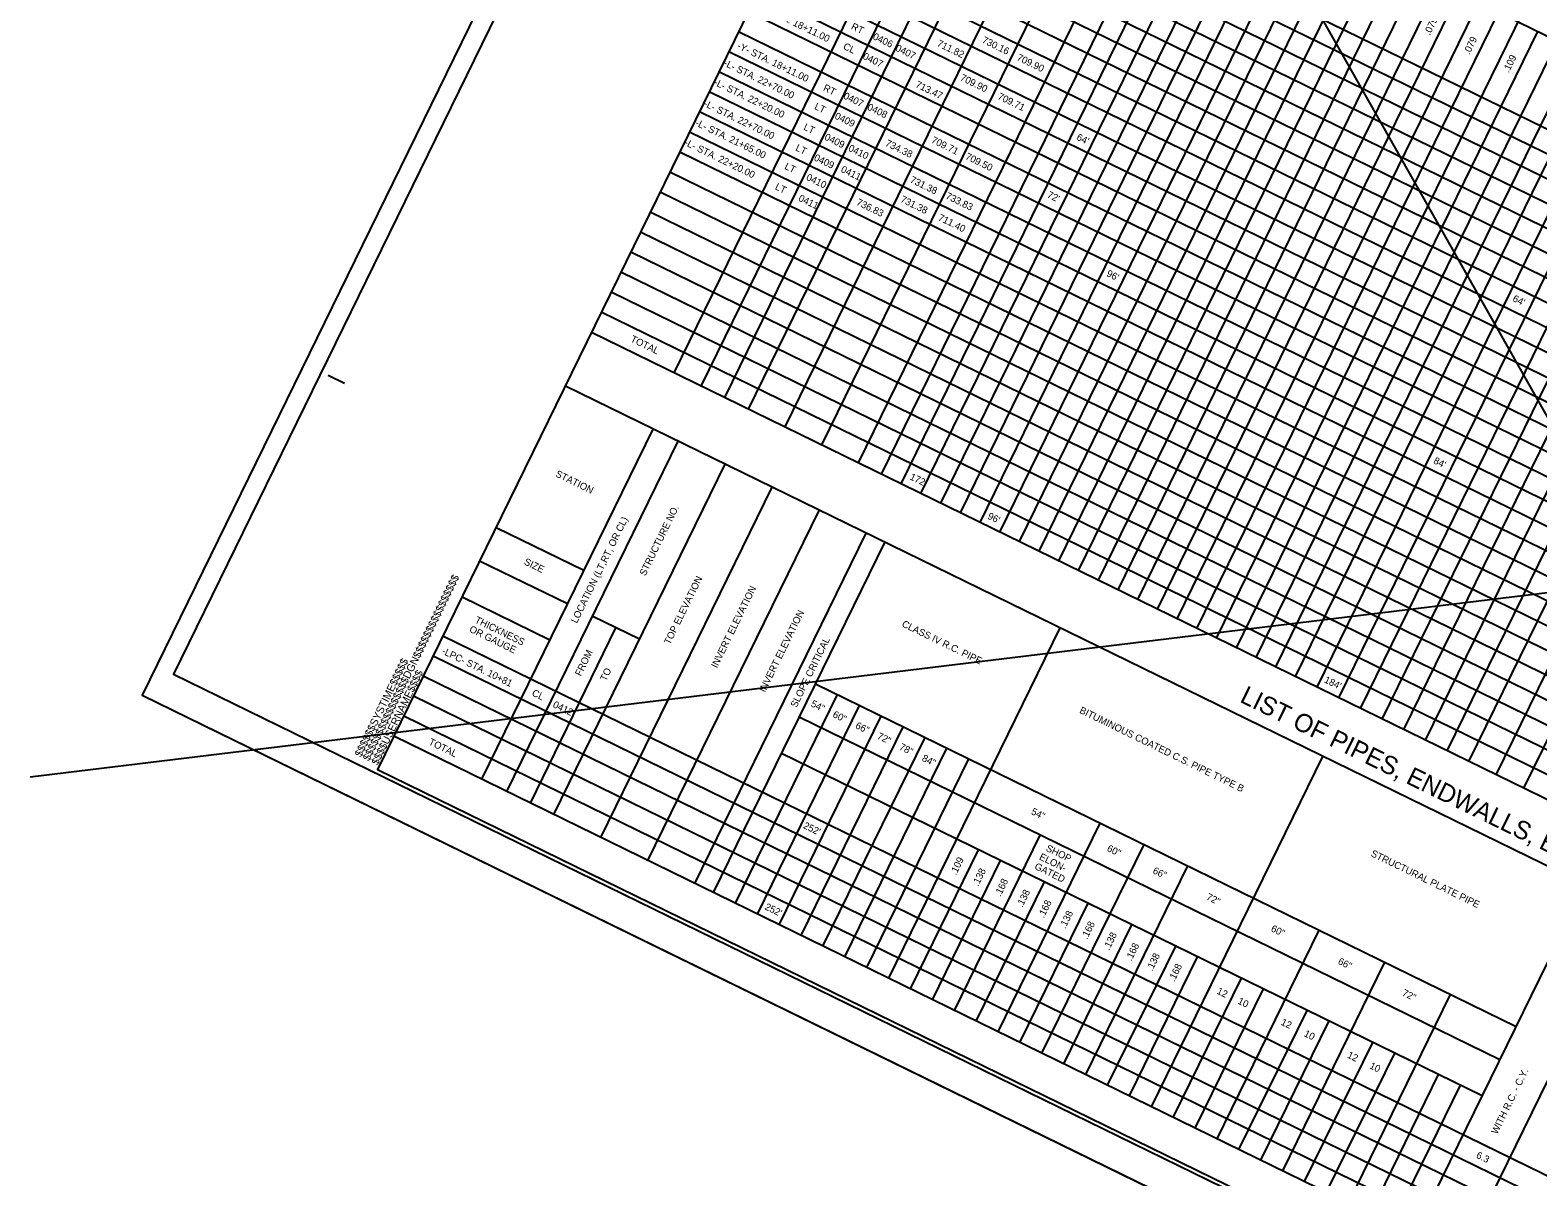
# Model space of a CAD drawing. Extents: x 1523741 to 1527628, y 632733 to 635404.
# Drawn here: x 1523741 to 1524772, y 634021 to 634805 of the extents above; entities that cross this region are included whole.
import ezdxf

# ---------------------------------------------------------------- set-up
doc = ezdxf.new("R2010")
doc.units = 0
for name, color, linetype in [('Scratch_Level_0', 7, 'Continuous'), ('Sheet Cutting Line CELL', 7, 'Continuous'), ('Sheet Pipe Summary CELL', 7, 'Continuous'), ('Sheet Pipe Summary Grid CELL', 7, 'Continuous'), ('Sheet Plot Border Inside CELL', 7, 'Continuous'), ('Sheet Plot Border Outside CELL', 7, 'Continuous'), ('Sheet Summary Combination CELL', 7, 'Continuous'), ('Sheet Summary Combination Grid CELL', 7, 'Continuous')]:
    doc.layers.add(name, color=color, linetype=linetype)

msp = doc.modelspace()

# ---------------------------------------------------------------- linework, layer by layer
at = {"layer": 'Scratch_Level_0'}
for p, q in [((1525401.8, 633436.6), (1524290.2, 635404.2)), ((1523740.9, 634294.4), (1525923.1, 634560))]:
    msp.add_line(p, q, dxfattribs=at)
at = {"layer": 'Sheet Cutting Line CELL'}
for p, q in [((1524300.8, 635338.5), (1523817.5, 634350.4)), ((1523817.5, 634350.4), (1525330.3, 633610.5))]:
    msp.add_line(p, q, dxfattribs=at)
at = {"layer": 'Sheet Pipe Summary Grid CELL'}
for p, q in [((1524181.3, 634570.7), (1524445.8, 635111.6)), ((1524199.7, 634561.7), (1524464.3, 635102.6)), ((1524231.9, 634546), (1524496.4, 635086.9)), ((1524257, 634533.7), (1524521.5, 635074.6)), ((1524282.1, 634521.4), (1524546.6, 635062.3)), ((1524307.2, 634509.1), (1524571.8, 635050)), ((1524323, 634501.4), (1524587.5, 635042.3)), ((1524376.9, 634475), (1524641.4, 635016)), ((1524430.8, 634448.7), (1524695.3, 634989.6)), ((1524215.8, 634553.8), (1524421.8, 634975)), ((1525653.1, 634309.3), (1524305.6, 634968.3)), ((1525646.4, 634295.6), (1524298.9, 634954.6)), ((1525639.7, 634281.9), (1524292.2, 634940.9)), ((1524336.4, 634494.8), (1524553.6, 634938.9)), ((1525633, 634268.2), (1524285.5, 634927.2)), ((1524349.9, 634488.2), (1524567.1, 634932.3)), ((1524363.4, 634481.6), (1524580.5, 634925.7)), ((1524376.9, 634475), (1524594, 634919.1)), ((1524930.5, 634726.3), (1524529, 634922.7)), ((1525626.3, 634254.4), (1524278.8, 634913.5)), ((1524390.3, 634468.5), (1524607.5, 634912.5)), ((1524403.8, 634461.9), (1524621, 634905.9)), ((1525619.6, 634240.7), (1524272.1, 634899.8)), ((1524417.3, 634455.3), (1524634.4, 634899.3)), ((1524605.9, 634363), (1524870.5, 634904)), ((1525612.9, 634227), (1524265.4, 634886.1)), ((1524444.2, 634442.1), (1524661.4, 634886.2)), ((1524457.7, 634435.5), (1524674.9, 634879.6)), ((1525606.2, 634213.3), (1524258.7, 634872.4)), ((1524471.2, 634428.9), (1524688.3, 634873)), ((1525599.5, 634199.6), (1524252, 634858.7)), ((1524498.1, 634415.7), (1524715.3, 634859.8)), ((1525592.8, 634185.9), (1524245.3, 634845)), ((1524484.7, 634422.3), (1524690.7, 634843.6)), ((1524525.1, 634402.6), (1524742.2, 634846.6)), ((1524724.5, 634305), (1524989.1, 634846.1)), ((1524552, 634389.4), (1524769.2, 634833.4)), ((1524743.1, 634295.9), (1525007.7, 634837)), ((1525586.1, 634172.2), (1524238.6, 634831.3)), ((1524511.6, 634409.1), (1524717.6, 634830.4)), ((1524762, 634286.7), (1525026.7, 634827.8)), ((1525579.4, 634158.5), (1524231.9, 634817.6)), ((1524538.6, 634396), (1524744.6, 634817.2)), ((1524579, 634376.2), (1524796.1, 634820.3)), ((1525572.7, 634144.8), (1524225.2, 634803.9)), ((1524565.5, 634382.8), (1524771.5, 634804.1)), ((1524620.8, 634355.8), (1524837.9, 634799.9)), ((1524635.6, 634348.5), (1524852.8, 634792.6)), ((1525566, 634131.1), (1524218.5, 634790.2)), ((1524592.5, 634369.6), (1524798.5, 634790.9)), ((1524650.4, 634341.3), (1524867.6, 634785.4)), ((1525559.3, 634117.4), (1524211.8, 634776.5)), ((1524665.2, 634334), (1524882.4, 634778.1)), ((1525552.6, 634103.7), (1524205.1, 634762.8)), ((1524680, 634326.8), (1524897.2, 634770.9)), ((1524694.9, 634319.5), (1524912, 634763.6)), ((1524709.7, 634312.3), (1524926.9, 634756.4)), ((1525545.9, 634090), (1524198.4, 634749.1)), ((1525539.2, 634076.3), (1524191.7, 634735.4)), ((1525532.5, 634062.6), (1524185, 634721.7)), ((1525525.8, 634048.9), (1524178.3, 634708)), ((1525519.1, 634035.2), (1524171.6, 634694.3)), ((1525512.4, 634021.5), (1524164.9, 634680.6)), ((1525505.7, 634007.8), (1524158.2, 634666.9)), ((1525499, 633994.1), (1524151.5, 634653.2)), ((1525492.3, 633980.4), (1524144.8, 634639.5)), ((1525485.6, 633966.7), (1524138.1, 634625.8)), ((1525478.9, 633953.1), (1524131.4, 634612.1)), ((1525478.9, 633953.1), (1524131.4, 634612.1)), ((1525472.2, 633939.4), (1524124.7, 634598.4)), ((1525472.2, 633939.4), (1524124.7, 634598.4))]:
    msp.add_line(p, q, dxfattribs=at)
at = {"layer": 'Sheet Plot Border Inside CELL'}
msp.add_lwpolyline([(1525799.6, 634580.5), (1524302.6, 635312.6), (1523839, 634364.8), (1525336.1, 633632.6)], close=True, dxfattribs=at)
at = {"layer": 'Sheet Plot Border Outside CELL'}
msp.add_lwpolyline([(1525813.5, 634598.6), (1524300.8, 635338.5), (1523817.5, 634350.4), (1525330.3, 633610.5)], close=True, dxfattribs=at)
at = {"layer": 'Sheet Summary Combination CELL'}
for p, q in [((1523944.7, 634569.2), (1523955.9, 634563.7)), ((1523978.5, 634299.4), (1523978.5, 634299.4))]:
    msp.add_line(p, q, dxfattribs=at)
msp.add_lwpolyline([(1525787.3, 634583.7), (1524439.8, 635242.7), (1523978.5, 634299.4), (1525326, 633640.4)], close=True, dxfattribs=at)
at = {"layer": 'Sheet Summary Combination Grid CELL'}
for p, q in [((1525454.3, 633902.8), (1524106.8, 634561.7)), ((1524049.7, 634292.8), (1524166.8, 634532.2)), ((1524066.8, 634284.4), (1524183.9, 634523.9)), ((1524098.9, 634268.8), (1524216, 634508.2)), ((1524131, 634253), (1524248.1, 634492.5)), ((1524163.2, 634237.3), (1524280.3, 634476.7)), ((1524119.4, 634435.5), (1524059.4, 634464.8)), ((1524195.4, 634221.6), (1524312.5, 634461)), ((1524208.1, 634215.3), (1524325.2, 634454.8)), ((1524108.3, 634412.7), (1524048.2, 634442)), ((1524096.2, 634388), (1524036.2, 634417.4)), ((1524157.5, 634388.6), (1524125.5, 634404.2)), ((1525370.6, 633731.7), (1524023.1, 634390.7)), ((1524082.9, 634276.6), (1524141.4, 634396.3)), ((1524327.9, 634156.8), (1524445, 634396.3)), ((1525363.9, 633718), (1524016.4, 634377)), ((1525357.2, 633704.3), (1524009.7, 634363.3)), ((1524265.1, 634364.1), (1524265.1, 634364.1)), ((1525350.5, 633690.6), (1524003, 634349.6)), ((1524221.8, 634357), (1524221.8, 634357)), ((1524223.1, 634208), (1524292.8, 634350.7)), ((1524277.9, 634358), (1524756.8, 634123.8)), ((1524238.1, 634200.7), (1524307.8, 634343.3)), ((1524254, 634341.3), (1524253.9, 634341.3)), ((1525343.8, 633676.9), (1523996.3, 634335.9)), ((1525343.8, 633676.9), (1523996.3, 634335.9)), ((1524253, 634193.4), (1524322.8, 634336)), ((1524745.7, 634101), (1524266.7, 634335.2)), ((1524268, 634186.1), (1524337.7, 634328.7)), ((1525337.1, 633663.2), (1523989.6, 634322.2)), ((1524282.9, 634178.7), (1524352.7, 634321.4)), ((1524733.6, 634076.3), (1524254.6, 634310.5)), ((1524297.9, 634171.4), (1524367.7, 634314.1)), ((1524507.5, 634068.9), (1524624.6, 634308.5)), ((1524312.9, 634164.1), (1524382.6, 634306.7)), ((1524402.7, 634120.2), (1524472.5, 634262.9)), ((1524372.8, 634134.8), (1524431.4, 634254.7)), ((1524432.6, 634105.5), (1524502.4, 634248.2)), ((1524342.8, 634149.5), (1524389.3, 634244.6)), ((1524357.8, 634142.1), (1524404.3, 634237.3)), ((1524462.6, 634090.9), (1524532.4, 634233.6)), ((1524387.7, 634127.5), (1524434.3, 634222.7)), ((1524687, 633981.1), (1524804.2, 634220.6)), ((1524417.6, 634112.9), (1524464.2, 634208)), ((1524447.6, 634098.2), (1524494.1, 634193.4)), ((1524552.3, 634047), (1524622.1, 634189.7)), ((1524477.5, 634083.6), (1524524.1, 634178.7)), ((1524492.5, 634076.3), (1524539, 634171.4)), ((1524597.3, 634025), (1524667.1, 634167.7)), ((1524522.4, 634061.6), (1524569, 634156.8)), ((1524537.4, 634054.3), (1524584, 634149.5)), ((1524642.2, 634003), (1524711.9, 634145.7)), ((1524567.3, 634039.6), (1524613.9, 634134.8)), ((1524719, 633965.5), (1524803.6, 634138.6)), ((1524582.3, 634032.3), (1524628.9, 634127.6)), ((1524612.2, 634017.7), (1524658.8, 634112.9)), ((1524627.2, 634010.4), (1524673.8, 634105.6)), ((1524657.1, 633995.7), (1524703.7, 634091)), ((1524672.1, 633988.4), (1524718.7, 634083.6))]:
    msp.add_line(p, q, dxfattribs=at)

# ---------------------------------------------------------------- texts
at = {"layer": 'Sheet Pipe Summary CELL'}
for s, p in [('.079', (1524697.8, 634801.2)), ('.079', (1524724.8, 634787.9)), ('.109', (1524751.7, 634775.5))]:
    msp.add_text(s, height=4.8, rotation=63.9377, dxfattribs=at).set_placement(p)
at = {"layer": 'Sheet Summary Combination CELL'}
for s, height, rotation, p in [('-Y- STA. 18+11.00', 4.8, 333.9377, (1524238.2, 634820.1)), ('RT', 4.8, 333.9377, (1524301.7, 634806)), ('0406', 4.8, 333.9377, (1524316.5, 634799.1)), ('-Y- STA. 18+11.00', 4.8, 333.9377, (1524223.8, 634792.8)), ('CL', 4.8, 333.9377, (1524296.3, 634792.4)), ('0407', 4.8, 333.9377, (1524332, 634791.2)), ('711.82', 4.8, 333.9377, (1524360.4, 634794.4)), ('730.16', 4.8, 333.9377, (1524391.2, 634796.7)), ('-L- STA. 22+70.00', 4.8, 333.9377, (1524214.6, 634781)), ('0407', 4.8, 333.9377, (1524309.7, 634785.6)), ('709.90', 4.8, 333.9377, (1524415, 634784.8)), ('709.90', 4.8, 333.9377, (1524376.3, 634771)), ('-L- STA. 22+20.00', 4.8, 333.9377, (1524207.9, 634767.9)), ('RT', 4.8, 333.9377, (1524282.6, 634764)), ('0407', 4.8, 333.9377, (1524296.4, 634758.5)), ('713.47', 4.8, 333.9377, (1524345.7, 634766.3)), ('709.71', 4.8, 333.9377, (1524401.9, 634758.2)), ('-L- STA. 22+70.00', 4.8, 333.9377, (1524201, 634753.3)), ('LT', 4.8, 333.9377, (1524276.6, 634751.3)), ('0408', 4.8, 333.9377, (1524312.7, 634750.9)), ('-L- STA. 21+65.00', 4.8, 333.9377, (1524195.2, 634740.1)), ('LT', 4.8, 333.9377, (1524269.2, 634737.2)), ('0409', 4.8, 333.9377, (1524290.5, 634744.8)), ('0409', 4.8, 333.9377, (1524283.5, 634730.4)), ('734.38', 4.8, 333.9377, (1524325.1, 634726.2)), ('709.71', 4.8, 333.9377, (1524356.5, 634728.3)), ("64'", 4.8, 333.9377, (1524455.8, 634730.3)), ('-L- STA. 22+20.00', 4.8, 333.9377, (1524187.7, 634726.7)), ('LT', 4.8, 333.9377, (1524263.7, 634723)), ('0409', 4.8, 333.9377, (1524276.3, 634716.3)), ('0410', 4.8, 333.9377, (1524299.8, 634722.8)), ('709.50', 4.8, 333.9377, (1524379.8, 634717.1)), ('LT', 4.8, 333.9377, (1524256.2, 634710.4)), ('0411', 4.8, 333.9377, (1524294.7, 634708.3)), ('LT', 4.8, 333.9377, (1524249.7, 634696.4)), ('0410', 4.8, 333.9377, (1524271, 634702.9)), ('731.38', 4.8, 333.9377, (1524342, 634701.2)), ('0411', 4.8, 333.9377, (1524265.7, 634688.6)), ('736.83', 4.8, 333.9377, (1524305.3, 634685.8)), ('731.38', 4.8, 333.9377, (1524335.4, 634687.8)), ('733.83', 4.8, 333.9377, (1524366.3, 634690.1)), ("72'", 4.8, 333.9377, (1524435.7, 634690.9)), ('711.40', 4.8, 333.9377, (1524361.2, 634675.3)), ("96'", 4.8, 333.9377, (1524476.3, 634637.1)), ("64'", 4.8, 333.9377, (1524753.9, 634620)), ('TOTAL', 4.8, 333.9377, (1524150.9, 634592.3)), ('STATION', 4.8, 333.9377, (1524099.6, 634500.1)), ("84'", 4.8, 333.9377, (1524699.8, 634509.1)), ("172'", 4.8, 333.9377, (1524341.8, 634498.1)), ('STRUCTURE NO.', 4.8, 63.9377, (1524161.5, 634431.5)), ("96'", 4.8, 333.9377, (1524395, 634471.2)), ('LOCATION (LT,RT, OR CL)', 4.8, 63.9377, (1524114.7, 634399.1)), ('SIZE', 4.8, 333.9377, (1524078.1, 634440)), ('$$$$$$$$$$$$$$$$DGN$$$$$$$$$$$$$$$$', 5.25, 63.9377, (1523972.7, 634304.9)), ('TOP ELEVATION', 4.8, 63.9377, (1524178.3, 634384.5)), ('INVERT ELEVATION', 4.8, 63.9377, (1524210.5, 634368.5)), ('THICKNESS', 4.8, 333.9377, (1524044.5, 634400.2)), ('INVERT ELEVATION', 4.8, 63.9377, (1524243.3, 634351.9)), ('CLASS IV R.C. PIPE', 4.8, 333.9377, (1524336.4, 634397.5)), ('OR GAUGE', 4.8, 333.9377, (1524040.7, 634393.9)), ('-LPC- STA. 10+81', 4.8, 333.9377, (1524021.9, 634379)), ('FROM', 4.8, 63.9377, (1524117.4, 634362.9)), ('SLOPE CRITICAL', 4.8, 63.9377, (1524264.8, 634341.4)), ('$$$$$$SYSTIME$$$$$', 5.25, 63.9377, (1523967.2, 634307.6)), ('$$$$USERNAME$$$$', 5.25, 63.9377, (1523978.6, 634302.1)), ('TO', 4.8, 63.9377, (1524134.6, 634359.5)), ("184'", 4.8, 333.9377, (1524625.1, 634359.3)), ('CL', 4.8, 333.9377, (1524083.5, 634350.3)), ('LIST OF PIPES, ENDWALLS, ETC. (FOR PIPES 54" & OVER)', 12.5, 333.9377, (1524567.2, 634346)), ('0412', 4.8, 333.9377, (1524097.8, 634342.3)), ('54"', 4.8, 333.9377, (1524274.2, 634342.9)), ('60"', 4.8, 333.9377, (1524289.1, 634335.6)), ('BITUMINOUS COATED C.S. PIPE TYPE B', 4.8, 333.9377, (1524457.8, 634338.4)), ('66"', 4.8, 333.9377, (1524304.6, 634328)), ('TOTAL', 4.8, 333.9377, (1524012.9, 634316.8)), ('72"', 4.8, 333.9377, (1524319.5, 634320.8)), ('78"', 4.8, 333.9377, (1524334.6, 634313.4)), ('84"', 4.8, 333.9377, (1524350.1, 634305.7)), ('54"', 4.8, 333.9377, (1524424.8, 634269.2)), ("252'", 4.8, 333.9377, (1524269, 634259.6)), ('SHOP', 4.8, 333.9377, (1524434.9, 634244.1)), ('60"', 4.8, 333.9377, (1524476.6, 634244)), ('.109', 4.8, 63.9377, (1524373.9, 634226.9)), ('ELON-', 4.8, 333.9377, (1524430.3, 634238.2)), ('STRUCTURAL PLATE PIPE', 4.8, 333.9377, (1524657, 634240.5)), ('.138', 4.8, 63.9377, (1524389, 634219.3)), ('GATED', 4.8, 333.9377, (1524427.1, 634231.7)), ('66"', 4.8, 333.9377, (1524507.9, 634228.8)), ('.168', 4.8, 63.9377, (1524404.2, 634212.2)), ('.138', 4.8, 63.9377, (1524419.2, 634204.7)), ('72"', 4.8, 333.9377, (1524544.5, 634210.8)), ("252'", 4.8, 333.9377, (1524242.7, 634204.1)), ('.168', 4.8, 63.9377, (1524433.9, 634197.6)), ('.138', 4.8, 63.9377, (1524448.6, 634190.3)), ('.168', 4.8, 63.9377, (1524463.5, 634183)), ('.138', 4.8, 63.9377, (1524478.6, 634175.6)), ('60"', 4.8, 333.9377, (1524588.7, 634189.2)), ('.168', 4.8, 63.9377, (1524493.8, 634168.2)), ('.138', 4.8, 63.9377, (1524508, 634161.3)), ('.168', 4.8, 63.9377, (1524523.1, 634154)), ('66"', 4.8, 333.9377, (1524634.5, 634166.8)), ('12', 4.8, 333.9377, (1524551.7, 634146.4)), ('10', 4.8, 333.9377, (1524566, 634139.6)), ('72"', 4.8, 333.9377, (1524678.4, 634145.2)), ('12', 4.8, 333.9377, (1524595.5, 634125.2)), ('10', 4.8, 333.9377, (1524611.3, 634117.4)), ('12', 4.8, 333.9377, (1524640.9, 634102.7)), ('10', 4.8, 333.9377, (1524656.1, 634095.4)), ('WITH R.C. - C.Y.', 4.8, 63.9377, (1524743.8, 634049.7)), ('6.3', 4.8, 333.9377, (1524729, 634034.2))]:
    msp.add_text(s, height=height, rotation=rotation, dxfattribs=at).set_placement(p)

doc.saveas('drawing.dxf')
